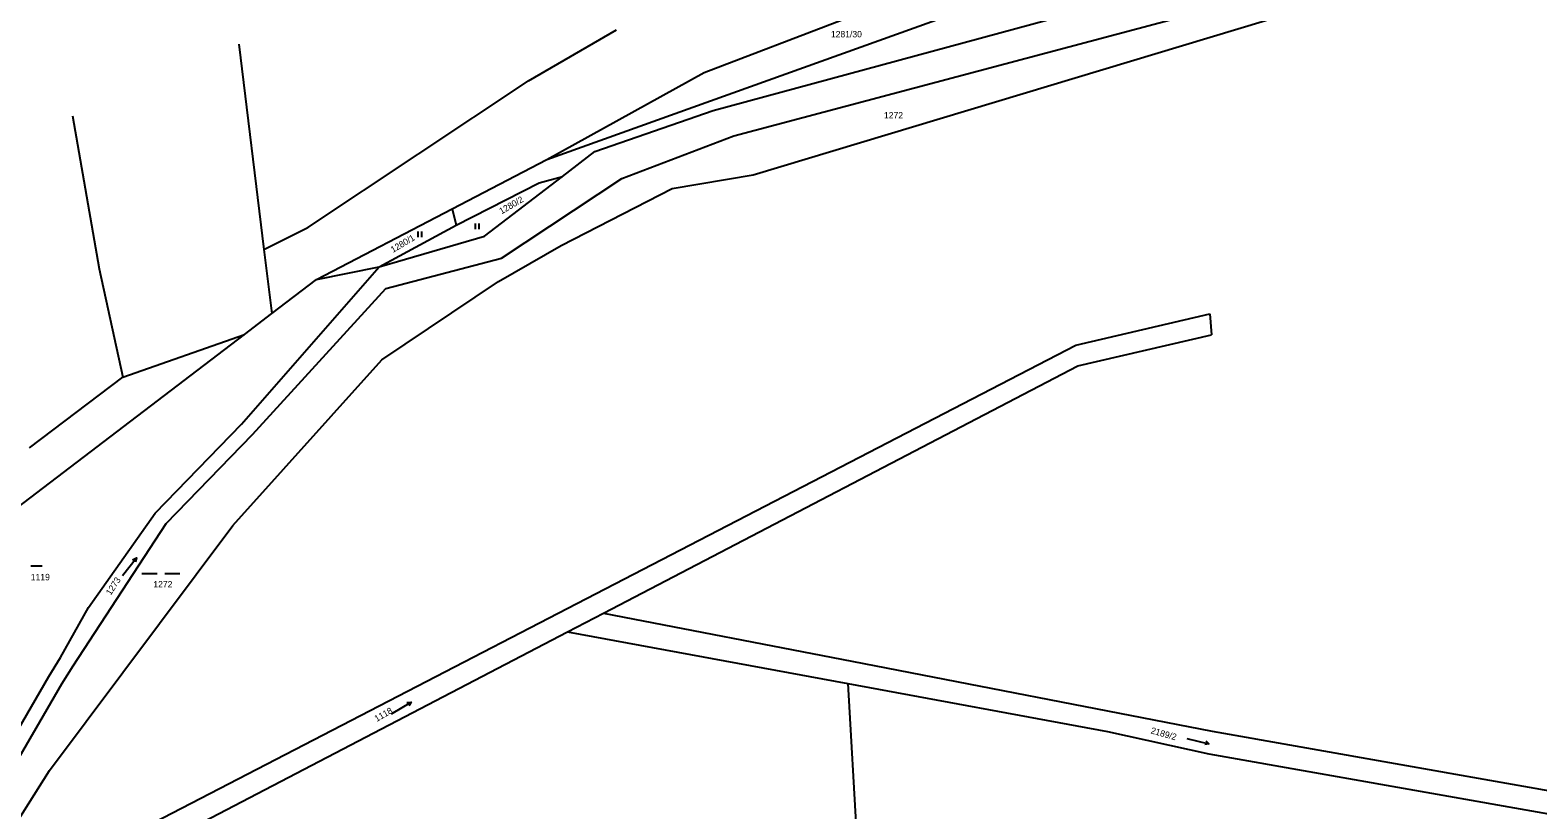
# Model space of a CAD drawing. Extents: x -779596 to -776743, y -1030330 to -1024513.
# Drawn here: x -778186.9 to -777787, y -1026146.3 to -1025939.4 of the extents above; entities that cross this region are included whole.
import ezdxf

# ---------------------------------------------------------------- set-up
doc = ezdxf.new("R2010")
doc.units = 0
for name, color, linetype in [('hranice parcel', 7, 'Continuous'), ('kultura', 7, 'Continuous'), ('č_ parcel šipka', 7, 'Continuous'), ('č_parcel poz_', 7, 'Continuous')]:
    doc.layers.add(name, color=color, linetype=linetype)

msp = doc.modelspace()

# ---------------------------------------------------------------- linework, layer by layer
at = {"layer": 'hranice parcel'}
for points in [[(-778005.71, -1025960.75), (-777787.1, -1025901.38)], [(-778000.3, -1025967.5), (-777780.29, -1025908.9)], [(-777995.13, -1025977.79), (-777781.21, -1025913.31)], [(-778049.89, -1025973.74), (-777893.75, -1025917.65)], [(-778008.12, -1025950.71), (-777971.06, -1025936.52)], [(-778054.68, -1025952.86), (-778031.4, -1025939.32)], [(-778131.542, -1025943.145), (-778124.88, -1025997.66)], [(-778049.89, -1025973.74), (-778008.12, -1025950.71)], [(-778113.2, -1025991.81), (-778054.68, -1025952.86)], [(-778175.621, -1025962.196), (-778168.57, -1026002.78)], [(-778037.1, -1025971.63), (-778005.71, -1025960.75)], [(-778029.98, -1025978.76), (-778000.3, -1025967.5)], [(-778074.94, -1025986.81), (-778049.89, -1025973.74)], [(-778045.7, -1025978.24), (-778037.1, -1025971.63)], [(-778066.35, -1025994.13), (-778045.7, -1025978.24)], [(-778061.92, -1025999.96), (-778029.98, -1025978.76)], [(-778051.89, -1025979.98), (-778045.7, -1025978.24)], [(-778016.58, -1025981.48), (-777995.13, -1025977.79)], [(-778073.88, -1025991.19), (-778051.89, -1025979.98)], [(-778046.03, -1025996.61), (-778016.58, -1025981.48)], [(-778110.94, -1026005.6), (-778074.94, -1025986.81)], [(-778074.94, -1025986.81), (-778073.88, -1025991.19)], [(-778124.88, -1025997.66), (-778113.2, -1025991.81)], [(-778094.31, -1026002.24), (-778073.88, -1025991.19)], [(-778094.31, -1026002.24), (-778066.35, -1025994.13)], [(-778124.88, -1025997.66), (-778122.8, -1026014.64)], [(-778062.71, -1026006.12), (-778046.03, -1025996.61)], [(-778168.57, -1026002.78), (-778162.28, -1026031.48)], [(-778130.82, -1026043.94), (-778094.31, -1026002.24)], [(-778110.94, -1026005.6), (-778094.31, -1026002.24)], [(-778092.55, -1026008), (-778061.92, -1025999.96)], [(-778122.8, -1026014.64), (-778110.94, -1026005.6)], [(-778093.64, -1026026.86), (-778062.71, -1026006.12)], [(-778127.96, -1026046.72), (-778092.55, -1026008)], [(-778130.01, -1026020.14), (-778122.8, -1026014.64)], [(-777909.6, -1026023), (-777874, -1026014.7)], [(-777874, -1026014.7), (-777873.6, -1026020.3)], [(-778201.2, -1026074.4), (-778130.01, -1026020.14)], [(-778162.28, -1026031.48), (-778130.01, -1026020.14)], [(-777909, -1026028.5), (-777873.6, -1026020.3)], [(-778216.64, -1026181.98), (-777909.6, -1026023)], [(-778133.17, -1026070.83), (-778093.64, -1026026.86)], [(-778034.82, -1026094.09), (-777909, -1026028.5)], [(-778187.07, -1026050.2), (-778162.28, -1026031.48)], [(-778153.7, -1026067.55), (-778130.82, -1026043.94)], [(-778150.83, -1026070.33), (-778127.96, -1026046.72)], [(-778175.52, -1026108.07), (-778150.83, -1026070.33)], [(-778171.39, -1026092.64), (-778153.7, -1026067.55)], [(-778181.76, -1026135.81), (-778133.17, -1026070.83)], [(-778178.86, -1026105.88), (-778171.39, -1026092.64)], [(-778044.35, -1026099.06), (-778034.82, -1026094.09)], [(-778034.82, -1026094.09), (-777968.98, -1026106.87)], [(-778217.21, -1026189.17), (-778044.35, -1026099.06)], [(-778044.35, -1026099.06), (-777970.07, -1026112.77)], [(-778181.93, -1026110.86), (-778178.86, -1026105.88)], [(-778178.48, -1026112.86), (-778175.52, -1026108.07)], [(-777968.98, -1026106.87), (-777873.37, -1026125.43)], [(-778197.13, -1026137.1), (-778181.93, -1026110.86)], [(-778193.68, -1026139.1), (-778178.48, -1026112.86)], [(-777970.07, -1026112.77), (-777901.12, -1026125.5)], [(-777970.07, -1026112.77), (-777967.67, -1026154.31)], [(-777901.12, -1026125.5), (-777874.32, -1026131.38)], [(-777873.37, -1026125.43), (-777774.8, -1026142.87)], [(-777874.32, -1026131.38), (-777756.15, -1026152.26)], [(-778191.39, -1026151.1), (-778181.76, -1026135.81)]]:
    msp.add_lwpolyline(points, dxfattribs=at)
at = {"layer": 'kultura'}
for points in [[(-778068.797, -1025992.205), (-778068.797, -1025990.705)], [(-778067.763, -1025992.205), (-778067.763, -1025990.705)], [(-778084.017, -1025994.375), (-778084.017, -1025992.875)], [(-778082.983, -1025994.375), (-778082.983, -1025992.875)], [(-778186.71, -1026081.53), (-778183.71, -1026081.53)], [(-778162.423, -1026084.141), (-778158.697, -1026079.439)], [(-778159.71, -1026079.913), (-778158.697, -1026079.439), (-778158.926, -1026080.534)], [(-778157.245, -1026083.58), (-778153.225, -1026083.58)], [(-778151.214, -1026083.58), (-778147.194, -1026083.58)], [(-778091.065, -1026120.764), (-778085.875, -1026117.756)], [(-778086.991, -1026117.825), (-778085.875, -1026117.756), (-778086.489, -1026118.69)], [(-777880.085, -1026127.315), (-777874.255, -1026128.725)], [(-777875.109, -1026128.005), (-777874.255, -1026128.725), (-777875.344, -1026128.976)]]:
    msp.add_lwpolyline(points, dxfattribs=at)

# ---------------------------------------------------------------- texts
at = {"layer": 'č_ parcel šipka'}
msp.add_text('1272', height=1.7, dxfattribs=at).set_placement((-777960.44, -1025962.87))
msp.add_text('1273', height=1.7, rotation=57.00045, dxfattribs=at).set_placement((-778165.518, -1026089.494))
at = {"layer": 'č_parcel poz_'}
for s, p in [('1281/30', (-777974.51, -1025941.35)), ('1119', (-778186.72, -1026085.38)), ('1272', (-778154.22, -1026087.29))]:
    msp.add_text(s, height=1.7, dxfattribs=at).set_placement(p)
for s, rotation, p in [('1280/2', 30.20024, (-778061.878, -1025988.347)), ('1280/1', 30.70024, (-778090.661, -1025998.556)), ('1118', 29.70024, (-778094.976, -1026122.978)), ('2189/2', 344.20274, (-777889.814, -1026125.963))]:
    msp.add_text(s, height=1.7, rotation=rotation, dxfattribs=at).set_placement(p)

doc.saveas('drawing.dxf')
